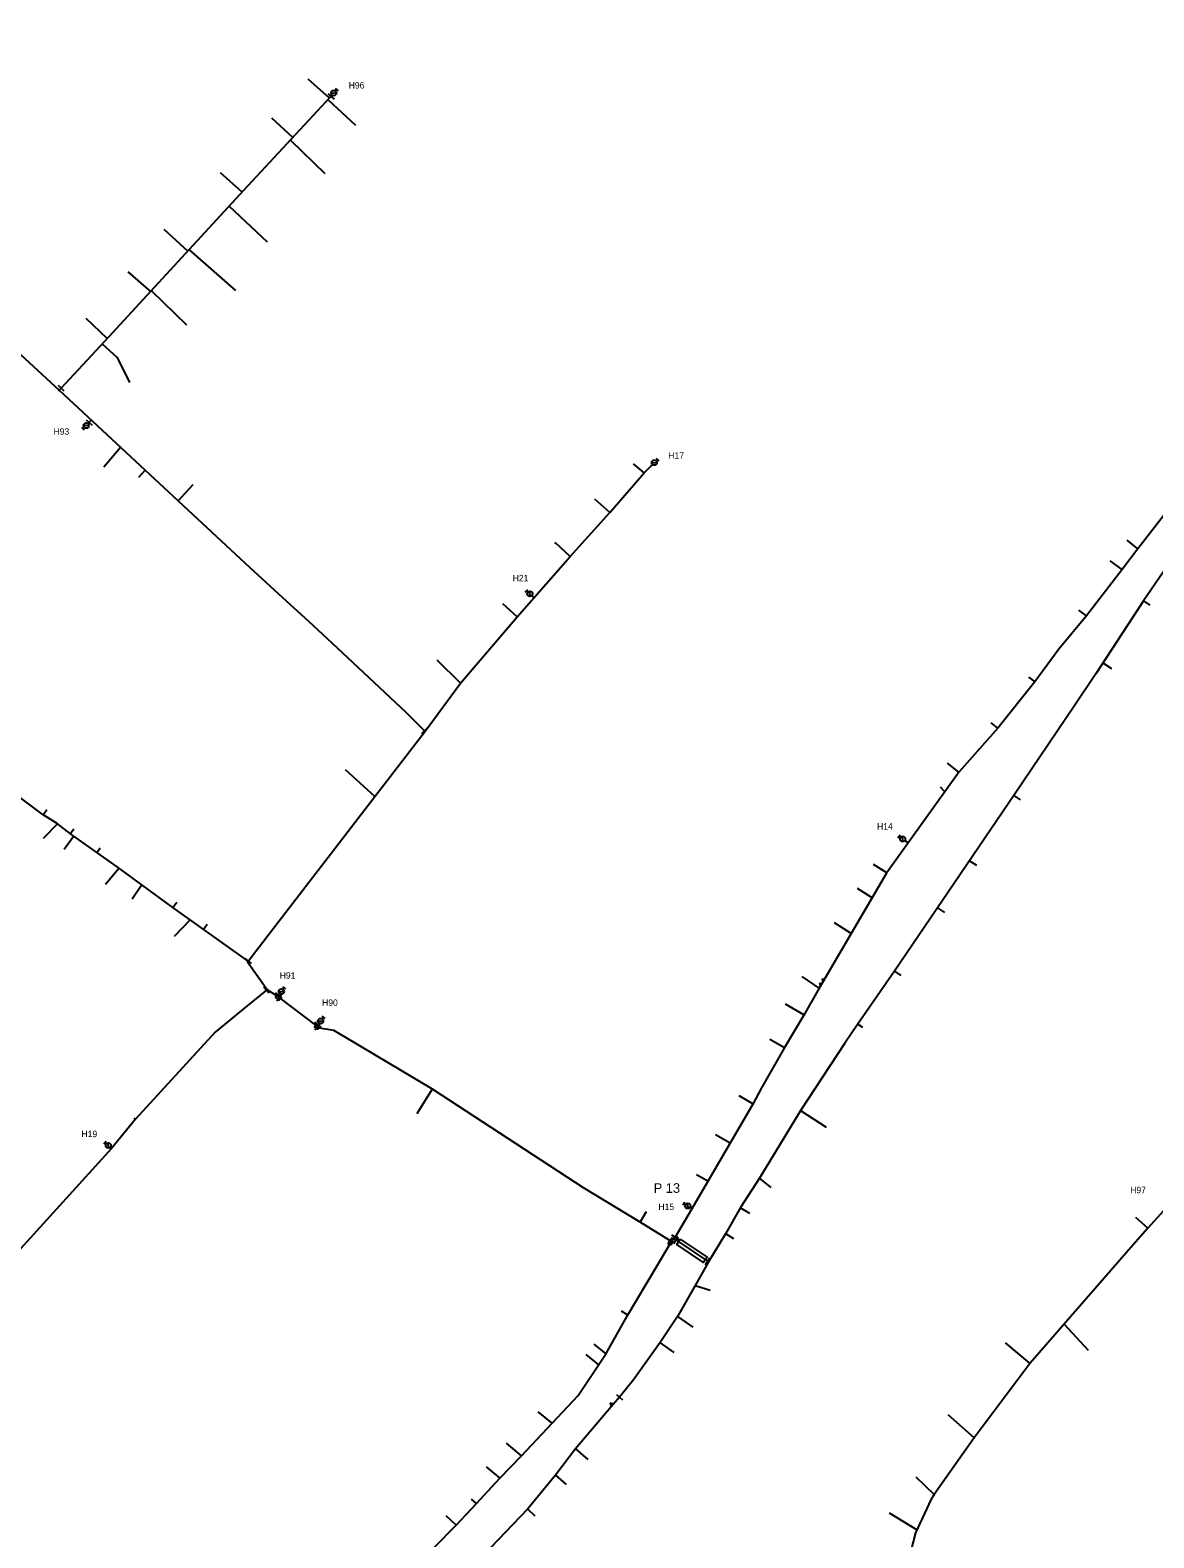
# Model space of a CAD drawing. Extents: x -548873 to -538270, y -1201997 to -1192514.
# Drawn here: x -547314.4 to -546963.5, y -1195490.5 to -1195019.8 of the extents above; entities that cross this region are included whole.
import ezdxf

# ---------------------------------------------------------------- set-up
doc = ezdxf.new("R2010")
doc.units = 0
for name, color, linetype in [('KN_HRAN_STÁTNÍ', 7, 'Continuous'), ('KN_PARC_Č', 7, 'Continuous'), ('KN_VKP_HRAN_SPORNÁ', 7, 'Continuous'), ('PK_PARC_Čv', 7, 'Continuous'), ('Vrstva 29', 7, 'Continuous'), ('Vrstva 37', 7, 'Continuous'), ('Vrstva 39', 7, 'Continuous')]:
    doc.layers.add(name, color=color, linetype=linetype)

# ---------------------------------------------------------------- blocks, each defined once
blk = doc.blocks.new('160')
at = {"layer": 'KN_HRAN_STÁTNÍ'}
blk.add_circle((0, 0), 0.0458, dxfattribs=at)
blk = doc.blocks.new('147')
at = {"layer": 'KN_HRAN_STÁTNÍ'}
blk.add_line((0, 1.27), (0, -1.27), dxfattribs=at)
blk = doc.blocks.new('133')
at = {"layer": 'KN_HRAN_STÁTNÍ'}
for p, q in [((0.28, 0), (0, 0)), ((0.54, 0.58), (1.7, -0.58)), ((1.94, 0), (2.52, 0)), ((2.52, 0.58), (2.52, -0.58))]:
    blk.add_line(p, q, dxfattribs=at)
blk.add_circle((1.11, 0), 0.825, dxfattribs=at)
blk = doc.blocks.new('150')
at = {"layer": 'KN_HRAN_STÁTNÍ'}
blk.add_line((0, 1.27), (0, -1.27), dxfattribs=at)
blk = doc.blocks.new('123')
at = {"layer": 'KN_HRAN_STÁTNÍ'}
for p, q in [((-0.26, 0.96), (0.26, 0.96)), ((-0.19, 1.13), (0.19, 0.79)), ((-0.19, 0.79), (0, 0.96)), ((0, 1.22), (0, 0.96)), ((0, 0.96), (0.19, 1.13)), ((0, 0.96), (0, 0))]:
    blk.add_line(p, q, dxfattribs=at)
blk = doc.blocks.new('128')
at = {"layer": 'KN_HRAN_STÁTNÍ'}
for p, q in [((-0.19, 1.06), (-0.43, 1.15)), ((-0.36, 0.84), (-0.19, 1.06)), ((-0.19, 1.06), (-0.02, 1.25)), ((-0.19, 1.06), (0, 0)), ((0.05, 0.95), (-0.19, 1.06)), ((-0.1, 1), (0.41, 0.91)), ((-0.07, 0.82), (0.17, 0.96)), ((0.17, 0.96), (-0.02, 1.13)), ((0.17, 0.96), (0, 0)), ((0.19, 1.21), (0.17, 0.96)), ((0.17, 0.96), (0.38, 1.08)), ((0.36, 0.77), (0.17, 0.96))]:
    blk.add_line(p, q, dxfattribs=at)

msp = doc.modelspace()

# ---------------------------------------------------------------- linework, layer by layer
at = {"layer": 'KN_PARC_Č'}
for points in [[(-547220.983, -1195041.033), (-547227.58, -1195035.058)], [(-547221.403, -1195041.485), (-547212.814, -1195049.436)], [(-547232.404, -1195053.314), (-547238.924, -1195047.207)], [(-547233.13, -1195054.095), (-547222.394, -1195064.569)], [(-547248.255, -1195070.366), (-547254.951, -1195064.295)], [(-547252.271, -1195074.735), (-547240.367, -1195085.872)], [(-547265.135, -1195088.729), (-547272.522, -1195081.989)], [(-547264.753, -1195088.314), (-547250.33, -1195101.099)], [(-547276.766, -1195101.383), (-547283.797, -1195095.238)], [(-547276.564, -1195101.163), (-547265.64, -1195111.826)], [(-547290.357, -1195116.078), (-547296.938, -1195109.816)], [(-547291.912, -1195117.759), (-547287.206, -1195122.019), (-547283.381, -1195129.809)], [(-547286.206, -1195150.041), (-547291.435, -1195156.231)], [(-547122.634, -1195158.004), (-547126.002, -1195155.213)], [(-547278.508, -1195157.203), (-547280.533, -1195159.413)], [(-547268.226, -1195166.77), (-547263.473, -1195161.631)], [(-547133.399, -1195170.392), (-547138.075, -1195166.209)], [(-546968.533, -1195181.712), (-546971.889, -1195179.057)], [(-547145.792, -1195184.124), (-547150.336, -1195179.823), (-547150.656, -1195180.162)], [(-546973.423, -1195188.138), (-546977.172, -1195185.42)], [(-546966.699, -1195197.904), (-546964.767, -1195199.292)], [(-547162.328, -1195202.97), (-547166.857, -1195198.912)], [(-546984.576, -1195202.631), (-546986.896, -1195200.887)], [(-547180.02, -1195223.688), (-547187.344, -1195216.438)], [(-546979.418, -1195217.359), (-546976.768, -1195219.082)], [(-547000.636, -1195223.172), (-547002.563, -1195221.79)], [(-547012.184, -1195237.69), (-547014.359, -1195236.013)], [(-547024.41, -1195251.449), (-547027.99, -1195248.654)], [(-547206.747, -1195259.007), (-547215.982, -1195250.686)], [(-547028.804, -1195257.575), (-547030.177, -1195256.142)], [(-547007.28, -1195258.741), (-547005.219, -1195260.039)], [(-547005.473, -1195259.879), (-547005.306, -1195259.63)], [(-547310.351, -1195264.719), (-547309.172, -1195263.079)], [(-547305.887, -1195267.552), (-547310.378, -1195272.134)], [(-547301.884, -1195270.702), (-547300.761, -1195269.148)], [(-547300.822, -1195271.455), (-547303.847, -1195275.587)], [(-547293.639, -1195276.516), (-547292.602, -1195275.092)], [(-547286.662, -1195281.43), (-547290.905, -1195286.489)], [(-547046.928, -1195282.841), (-547051.085, -1195280.274)], [(-547021.102, -1195279.126), (-547018.866, -1195280.536)], [(-547279.585, -1195286.587), (-547282.545, -1195291.092)], [(-547051.521, -1195290.669), (-547056.085, -1195287.756)], [(-547269.867, -1195293.672), (-547268.665, -1195292.052)], [(-547031.073, -1195293.832), (-547028.88, -1195295.264)], [(-547264.429, -1195297.565), (-547269.4, -1195302.72)], [(-547260.333, -1195300.498), (-547259.163, -1195298.941)], [(-547058.037, -1195301.809), (-547063.266, -1195298.471)], [(-547068.009, -1195318.857), (-547073.338, -1195315.237)], [(-547044.46, -1195313.575), (-547042.496, -1195314.939)], [(-547072.77, -1195327.237), (-547078.558, -1195323.859)], [(-547055.997, -1195330.177), (-547054.509, -1195331.113)], [(-547078.831, -1195337.515), (-547083.391, -1195334.897)], [(-547188.838, -1195350.414), (-547193.657, -1195358.146)], [(-547088.695, -1195355.01), (-547093.022, -1195352.523)], [(-547073.836, -1195357.125), (-547065.851, -1195362.278)], [(-547281.558, -1195359.786), (-547281.95, -1195359.47)], [(-547095.867, -1195367.332), (-547100.374, -1195364.706)], [(-547102.768, -1195379.18), (-547106.285, -1195377.13)], [(-547086.713, -1195378.197), (-547083.087, -1195381.125)], [(-547123.945, -1195391.963), (-547121.994, -1195388.639)], [(-547092.597, -1195387.448), (-547089.827, -1195389.15)], [(-546965.426, -1195393.835), (-546969.177, -1195390.511)], [(-547097.276, -1195395.518), (-547094.761, -1195397.09)], [(-547106.714, -1195411.679), (-547102.02, -1195413.14)], [(-547127.815, -1195421.024), (-547129.741, -1195419.703)], [(-547112.221, -1195421.388), (-547107.468, -1195424.747)], [(-546991.547, -1195423.836), (-546984.016, -1195431.909)], [(-547136.837, -1195436.461), (-547140.771, -1195433.228)], [(-547134.569, -1195433.022), (-547138.255, -1195430.028)], [(-547117.668, -1195429.58), (-547113.379, -1195432.675)], [(-547002.167, -1195436.038), (-547009.842, -1195429.667)], [(-547151.425, -1195454.724), (-547155.778, -1195451.144)], [(-547019.582, -1195459.325), (-547027.693, -1195452.106)], [(-547160.961, -1195464.888), (-547165.644, -1195460.915)], [(-547144.081, -1195462.755), (-547140.308, -1195466.005)], [(-547167.675, -1195471.873), (-547171.862, -1195468.317)], [(-547150.4, -1195470.987), (-547147.005, -1195473.868)], [(-547032.076, -1195476.946), (-547037.756, -1195471.565)], [(-547175.084, -1195479.829), (-547176.561, -1195478.429)], [(-547181.364, -1195486.548), (-547184.461, -1195483.607)], [(-547159.092, -1195481.471), (-547156.777, -1195483.652)], [(-547037.524, -1195488.036), (-547046.056, -1195482.82)]]:
    msp.add_lwpolyline(points, dxfattribs=at)
at = {"layer": 'KN_VKP_HRAN_SPORNÁ'}
for points in [[(-546780.527, -1194991.909), (-546812.867, -1195020.779), (-546834.993, -1195040.53), (-546855.169, -1195058.541), (-546861.411, -1195064.113), (-546899.377, -1195098.211), (-546906.915, -1195105.578), (-546915.195, -1195114.339), (-546925.068, -1195125.489), (-546945.212, -1195151.716), (-546968.513, -1195181.686), (-546973.427, -1195188.143), (-546984.582, -1195202.639), (-546993.205, -1195213.077), (-547000.692, -1195223.248), (-547012.184, -1195237.69), (-547024.341, -1195251.353), (-547047.004, -1195282.946), (-547066.985, -1195317.105)], [(-547304.71, -1195131.59), (-547289.883, -1195115.566), (-547277.83, -1195102.54), (-547247.67, -1195069.73), (-547220.58, -1195040.6)], [(-547407.16, -1195188.22), (-547408.78, -1195186.5), (-547409.06, -1195184.71), (-547407.87, -1195183.42), (-547397.79, -1195173.9), (-547393.14, -1195170.06), (-547382.83, -1195159.23), (-547376.73, -1195152.92), (-547370.15, -1195146.53), (-547361.93, -1195137.68), (-547356.985, -1195132.487), (-547352.54, -1195127.82), (-547347.64, -1195122.46), (-547343.34, -1195118.13), (-547333.35, -1195107.66), (-547332.24, -1195107.45), (-547322.865, -1195116.088), (-547305.38, -1195132.2)], [(-547305.38, -1195132.2), (-547304.71, -1195131.59)], [(-547305.38, -1195132.2), (-547245.85, -1195187.59), (-547233.186, -1195199.15), (-547227.61, -1195204.24), (-547218.65, -1195212.51), (-547197.13, -1195232.75), (-547192.29, -1195237.55), (-547191.44, -1195238.34), (-547191.27, -1195238.5)], [(-547191.1, -1195238.67), (-547180.02, -1195223.688), (-547162.328, -1195202.97), (-547157.026, -1195196.927), (-547145.792, -1195184.124), (-547133.399, -1195170.392), (-547122.634, -1195158.004), (-547120.506, -1195155.843), (-547120.447, -1195155.783)], [(-546947.403, -1195170.755), (-546954.413, -1195180.05), (-546966.713, -1195197.925), (-546981.654, -1195220.778), (-546988.427, -1195230.812), (-547007.07, -1195258.431), (-547044.497, -1195313.63), (-547056.036, -1195330.233), (-547059.999, -1195336.091), (-547073.768, -1195357.014), (-547086.698, -1195378.174), (-547092.563, -1195387.39), (-547097.301, -1195395.561), (-547102.569, -1195404.372)], [(-547246.367, -1195310.496), (-547269.826, -1195293.702), (-547279.585, -1195286.587), (-547286.559, -1195281.503), (-547301.829, -1195270.746), (-547306, -1195267.463), (-547310.314, -1195264.746), (-547328.316, -1195251.3), (-547340.855, -1195241.935), (-547349.979, -1195235.404), (-547360.017, -1195227.356), (-547366.721, -1195222.746), (-547375.659, -1195215.551), (-547375.928, -1195215.344), (-547390.528, -1195204.112), (-547391.692, -1195203.177), (-547397.912, -1195196.751), (-547401.169, -1195193.786), (-547406.77, -1195188.61), (-547406.97, -1195188.42), (-547407.16, -1195188.22)], [(-547246.279, -1195310.382), (-547243.946, -1195307.35), (-547206.747, -1195259.007), (-547191.1, -1195238.67)], [(-547191.27, -1195238.5), (-547191.1, -1195238.67)], [(-547240.439, -1195319.394), (-547246.556, -1195310.729), (-547246.367, -1195310.496)], [(-547246.367, -1195310.496), (-547246.279, -1195310.382)], [(-547240.594, -1195319.52), (-547246.61, -1195324.43), (-547256.655, -1195332.627), (-547281.532, -1195359.754), (-547289.044, -1195368.93), (-547318.463, -1195401.456), (-547332.03, -1195418.311)], [(-547240.439, -1195319.394), (-547240.594, -1195319.52)], [(-547236.644, -1195321.84), (-547237.371, -1195321.295), (-547240.439, -1195319.394)], [(-547067.742, -1195318.4), (-547068.01, -1195318.858), (-547072.832, -1195327.346), (-547078.922, -1195337.669), (-547085.986, -1195350.044), (-547088.777, -1195355.16), (-547107.792, -1195387.806), (-547112.987, -1195396.686)], [(-547066.985, -1195317.105), (-547067.742, -1195318.4)], [(-547224.677, -1195330.869), (-547225.216, -1195330.423), (-547236.35, -1195322.06), (-547236.644, -1195321.84)], [(-547114.475, -1195397.801), (-547114.639, -1195397.7), (-547123.945, -1195391.963), (-547141.651, -1195381.202), (-547188.788, -1195350.443), (-547216.04, -1195334.23), (-547219.54, -1195332.1), (-547224.07, -1195331.37), (-547224.246, -1195331.225), (-547224.677, -1195330.869)], [(-546947.943, -1195374.483), (-546965.435, -1195393.845), (-546969.264, -1195398.243), (-547002.142, -1195436.005), (-547019.582, -1195459.325), (-547032.076, -1195476.946), (-547033.1, -1195478.39), (-547037.92, -1195488.9), (-547041.37, -1195502.14), (-547042.28, -1195506.03), (-547045.31, -1195509.717)], [(-547246.799, -1195560.024), (-547230.382, -1195541.268), (-547214.699, -1195524.527), (-547207.817, -1195516.586), (-547188.114, -1195493.446), (-547181.403, -1195486.59), (-547175.033, -1195479.774), (-547167.714, -1195471.913), (-547160.967, -1195464.894), (-547143.297, -1195446.062), (-547136.789, -1195436.389), (-547134.548, -1195432.99), (-547127.853, -1195421.088), (-547118.783, -1195405.857), (-547114.117, -1195398.022)], [(-547114.117, -1195398.022), (-547114.475, -1195397.801)], [(-547113.269, -1195397.167), (-547113.535, -1195396.975), (-547114.117, -1195398.022)], [(-547112.987, -1195396.686), (-547113.247, -1195397.131), (-547113.269, -1195397.167)], [(-547113.269, -1195397.167), (-547113.057, -1195397.321), (-547112.768, -1195397.515)], [(-547112.768, -1195397.515), (-547102.86, -1195404.177)], [(-547102.569, -1195404.372), (-547106.714, -1195411.679), (-547112.223, -1195421.391), (-547117.663, -1195429.572), (-547126.021, -1195441.229), (-547130.372, -1195446.567)], [(-547102.86, -1195404.177), (-547102.569, -1195404.372)], [(-547130.372, -1195446.567), (-547132.988, -1195449.593)], [(-547132.988, -1195449.593), (-547144.079, -1195462.753), (-547150.381, -1195470.964), (-547159.039, -1195481.415), (-547177.635, -1195500.911), (-547182.589, -1195506.258), (-547190.482, -1195514.777), (-547219.522, -1195544.405), (-547224.042, -1195549.648), (-547237.452, -1195565.2), (-547238.39, -1195566.304)]]:
    msp.add_lwpolyline(points, dxfattribs=at)
at = {"layer": 'PK_PARC_Čv'}
for points in [[(-547220.58, -1195040.6), (-547220.45, -1195040.46), (-547220.3, -1195040.28)], [(-547295.333, -1195141.548), (-547296.159, -1195142.418)], [(-547120.447, -1195155.783), (-547120.272, -1195155.605)], [(-547157.026, -1195196.927), (-547157.517, -1195196.499)], [(-547040.26, -1195273.544), (-547041.046, -1195272.961)], [(-547237.107, -1195321.493), (-547236.61, -1195320.829)], [(-547237.23, -1195321.12), (-547237.81, -1195321.84), (-547236.77, -1195322.62), (-547236.216, -1195321.881), (-547237.23, -1195321.12)], [(-547225.07, -1195330.23), (-547224.06, -1195330.98), (-547224.63, -1195331.73), (-547225.64, -1195330.98), (-547225.07, -1195330.23)], [(-547224.946, -1195330.646), (-547224.418, -1195330.006)], [(-547289.044, -1195368.93), (-547289.19, -1195368.792)], [(-547107.69, -1195387.631), (-547108.058, -1195387.424)], [(-547114.483, -1195397.426), (-547113.7, -1195397.87), (-547114.336, -1195399.004), (-547115.124, -1195398.557), (-547114.483, -1195397.426)]]:
    msp.add_lwpolyline(points, dxfattribs=at)
at = {"layer": 'Vrstva 37'}
msp.add_lwpolyline([(-547111.406, -1195397.226), (-547103.05, -1195402.844), (-547104.165, -1195404.504), (-547112.521, -1195398.886), (-547111.406, -1195397.226)], dxfattribs=at)

# ---------------------------------------------------------------- block references
at = {"layer": 'PK_PARC_Čv'}
for name, p, xscale, yscale, rotation in [('133', (-547220.3, -1195040.28), 1.000000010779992, 1.0000000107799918, 51.00000108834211), ('150', (-547220.45, -1195040.46), 1.0000000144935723, 1.0000000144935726, 49.00000089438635), ('133', (-547296.159, -1195142.418), 1.00000000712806, 1.00000000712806, -133.00000056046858), ('150', (-547296.014, -1195142.266), 1.00000000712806, 1.00000000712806, 46.99999943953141), ('133', (-547120.272, -1195155.605), 1.0000000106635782, 1.0000000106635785, 45.99999834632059), ('133', (-547157.517, -1195196.499), 1.0000000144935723, 1.0000000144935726, 139.00000089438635), ('133', (-547041.046, -1195272.961), 1.000000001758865, 1.000000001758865, 144.00000066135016), ('150', (-547236.828, -1195321.121), 1.000000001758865, 1.000000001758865, 54.00000066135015), ('133', (-547236.61, -1195320.829), 1.000000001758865, 1.000000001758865, 54.00000066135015), ('150', (-547224.674, -1195330.316), 1.000000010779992, 1.0000000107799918, 51.00000108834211), ('133', (-547224.418, -1195330.006), 1.000000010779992, 1.0000000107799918, 51.00000108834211), ('133', (-547289.19, -1195368.792), 1.00000000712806, 1.00000000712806, 136.99999943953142), ('133', (-547108.058, -1195387.424), 1.0037042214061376, 1.0037042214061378, 150.62079160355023)]:
    msp.add_blockref(name, p, dxfattribs=dict(at, xscale=xscale, yscale=yscale, rotation=rotation))
at = {"layer": 'Vrstva 29'}
for name, p, xscale, yscale, rotation in [('160', (-547220.58, -1195040.6), 1.0000000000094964, 1.0000000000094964, 47.99999869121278), ('147', (-547304.71, -1195131.59), 0.999999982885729, 0.9999999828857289, -135), ('160', (-547305.38, -1195132.2), 1.0000000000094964, 1.0000000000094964, 137.9999986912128), ('160', (-547120.447, -1195155.783), 1.0000000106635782, 1.0000000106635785, -134.00000165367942), ('147', (-547191.27, -1195238.5), 1.0000000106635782, 1.0000000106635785, 135.99999834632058), ('160', (-547191.1, -1195238.67), 0.9999999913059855, 0.9999999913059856, -127.00000193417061), ('147', (-547246.279, -1195310.382), 0.9999999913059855, 0.9999999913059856, -127.00000193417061), ('160', (-547246.367, -1195310.496), 1.000000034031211, 1.0000000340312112, 141.99999959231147), ('147', (-547240.594, -1195319.52), 1.0000000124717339, 1.0000000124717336, -139.99999868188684), ('160', (-547240.439, -1195319.394), 1.000191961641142, 1.000191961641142, -97.08900113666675), ('147', (-547236.644, -1195321.84), 1.000000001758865, 1.000000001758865, 144.00000066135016), ('160', (-547067.742, -1195318.4), 0.9999999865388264, 0.9999999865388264, 149.99999955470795), ('160', (-547066.985, -1195317.105), 0.9999999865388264, 0.9999999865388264, 149.99999955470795), ('147', (-547224.677, -1195330.869), 1.000000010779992, 1.0000000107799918, 141.00000108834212), ('147', (-547112.987, -1195396.686), 0.9999999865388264, 0.9999999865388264, -120.00000044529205), ('147', (-547114.475, -1195397.801), 1.0000000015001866, 1.0000000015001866, 149.00000017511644), ('160', (-547114.117, -1195398.022), 0.999999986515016, 0.9999999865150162, -164.99999987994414), ('147', (-547112.768, -1195397.515), 0.9999999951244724, 0.9999999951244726, 146.99999872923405), ('160', (-547113.269, -1195397.167), 1.000000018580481, 1.000000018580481, 144.99999976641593), ('147', (-547102.86, -1195404.177), 0.9999999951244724, 0.9999999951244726, 146.99999872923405), ('160', (-547102.569, -1195404.372), 1.0000000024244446, 1.0000000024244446, 104.00000032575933), ('147', (-547130.372, -1195446.567), 1.0000000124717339, 1.0000000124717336, 49.99999868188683), ('160', (-547132.988, -1195449.593), 1.0000000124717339, 1.0000000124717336, 49.99999868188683)]:
    msp.add_blockref(name, p, dxfattribs=dict(at, xscale=xscale, yscale=yscale, rotation=rotation))
at = {"layer": 'Vrstva 39'}
for name, p in [('123', (-547066.985, -1195317.105)), ('123', (-547067.742, -1195318.4)), ('128', (-547132.988, -1195449.593))]:
    msp.add_blockref(name, p, dxfattribs=at)

# ---------------------------------------------------------------- texts
at = {"layer": 'PK_PARC_Čv'}
for s, height, p in [('H96', 2, (-547214.94, -1195037.99)), ('H93', 2, (-547307.129, -1195146.078)), ('H17', 2, (-547115.13, -1195153.574)), ('H21', 2, (-547163.727, -1195191.849)), ('H14', 2, (-547049.956, -1195269.371)), ('H91', 2, (-547236.49, -1195315.939)), ('H90', 2, (-547223.258, -1195324.406)), ('H19', 2, (-547298.4, -1195365.412)), ('P 13', 3, (-547119.718, -1195382.794)), ('H97', 2, (-546970.894, -1195382.91)), ('H15', 2, (-547118.218, -1195388.164))]:
    msp.add_text(s, height=height, dxfattribs=at).set_placement(p)

doc.saveas('drawing.dxf')
